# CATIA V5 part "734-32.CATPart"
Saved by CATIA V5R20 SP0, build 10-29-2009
Part number: 734-32
Bounding box of the stored display mesh (mm): x -28 to 28, y -28 to 28, z -37 to 56
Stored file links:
  C:\Users\Utente\Desktop\IO LAVORO\3D X SITO CF\X SITO\734\734-32.CATPart
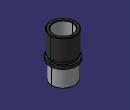
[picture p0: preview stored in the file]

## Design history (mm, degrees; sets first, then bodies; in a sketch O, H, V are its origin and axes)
Set1
  DatumSurface1 to DatumSurface25 "734-32"
Body1 (main body)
